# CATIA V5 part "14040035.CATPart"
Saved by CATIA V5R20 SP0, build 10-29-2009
Part number: 14040035
Definition: NONE
Nomenclature: 14040035
Source: Unknown
Description: 14040035
Bounding box of the stored display mesh (mm): x -17.5 to 70, y -34 to 23.924, z -24.1 to 24.1
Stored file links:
  C:\Users\Utente\Desktop\IO LAVORO\3D X SITO CF\X SITO\PLASTICA\RF2\14040035.CATPart
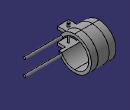
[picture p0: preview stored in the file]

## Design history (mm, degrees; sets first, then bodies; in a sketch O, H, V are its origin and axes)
Body1 "14040035" (main body)
  Solid1: solid without history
